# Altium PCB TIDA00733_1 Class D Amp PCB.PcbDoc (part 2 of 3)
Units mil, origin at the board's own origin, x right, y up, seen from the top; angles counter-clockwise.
Board outline 5700 x 4500 mil, 4 copper layers (Top Layer, Signal Layer 1, Signal Layer 2, Bottom Layer), stack 61.668 mil thick; 305 components, 186 nets, 894 pads, 1056 vias.
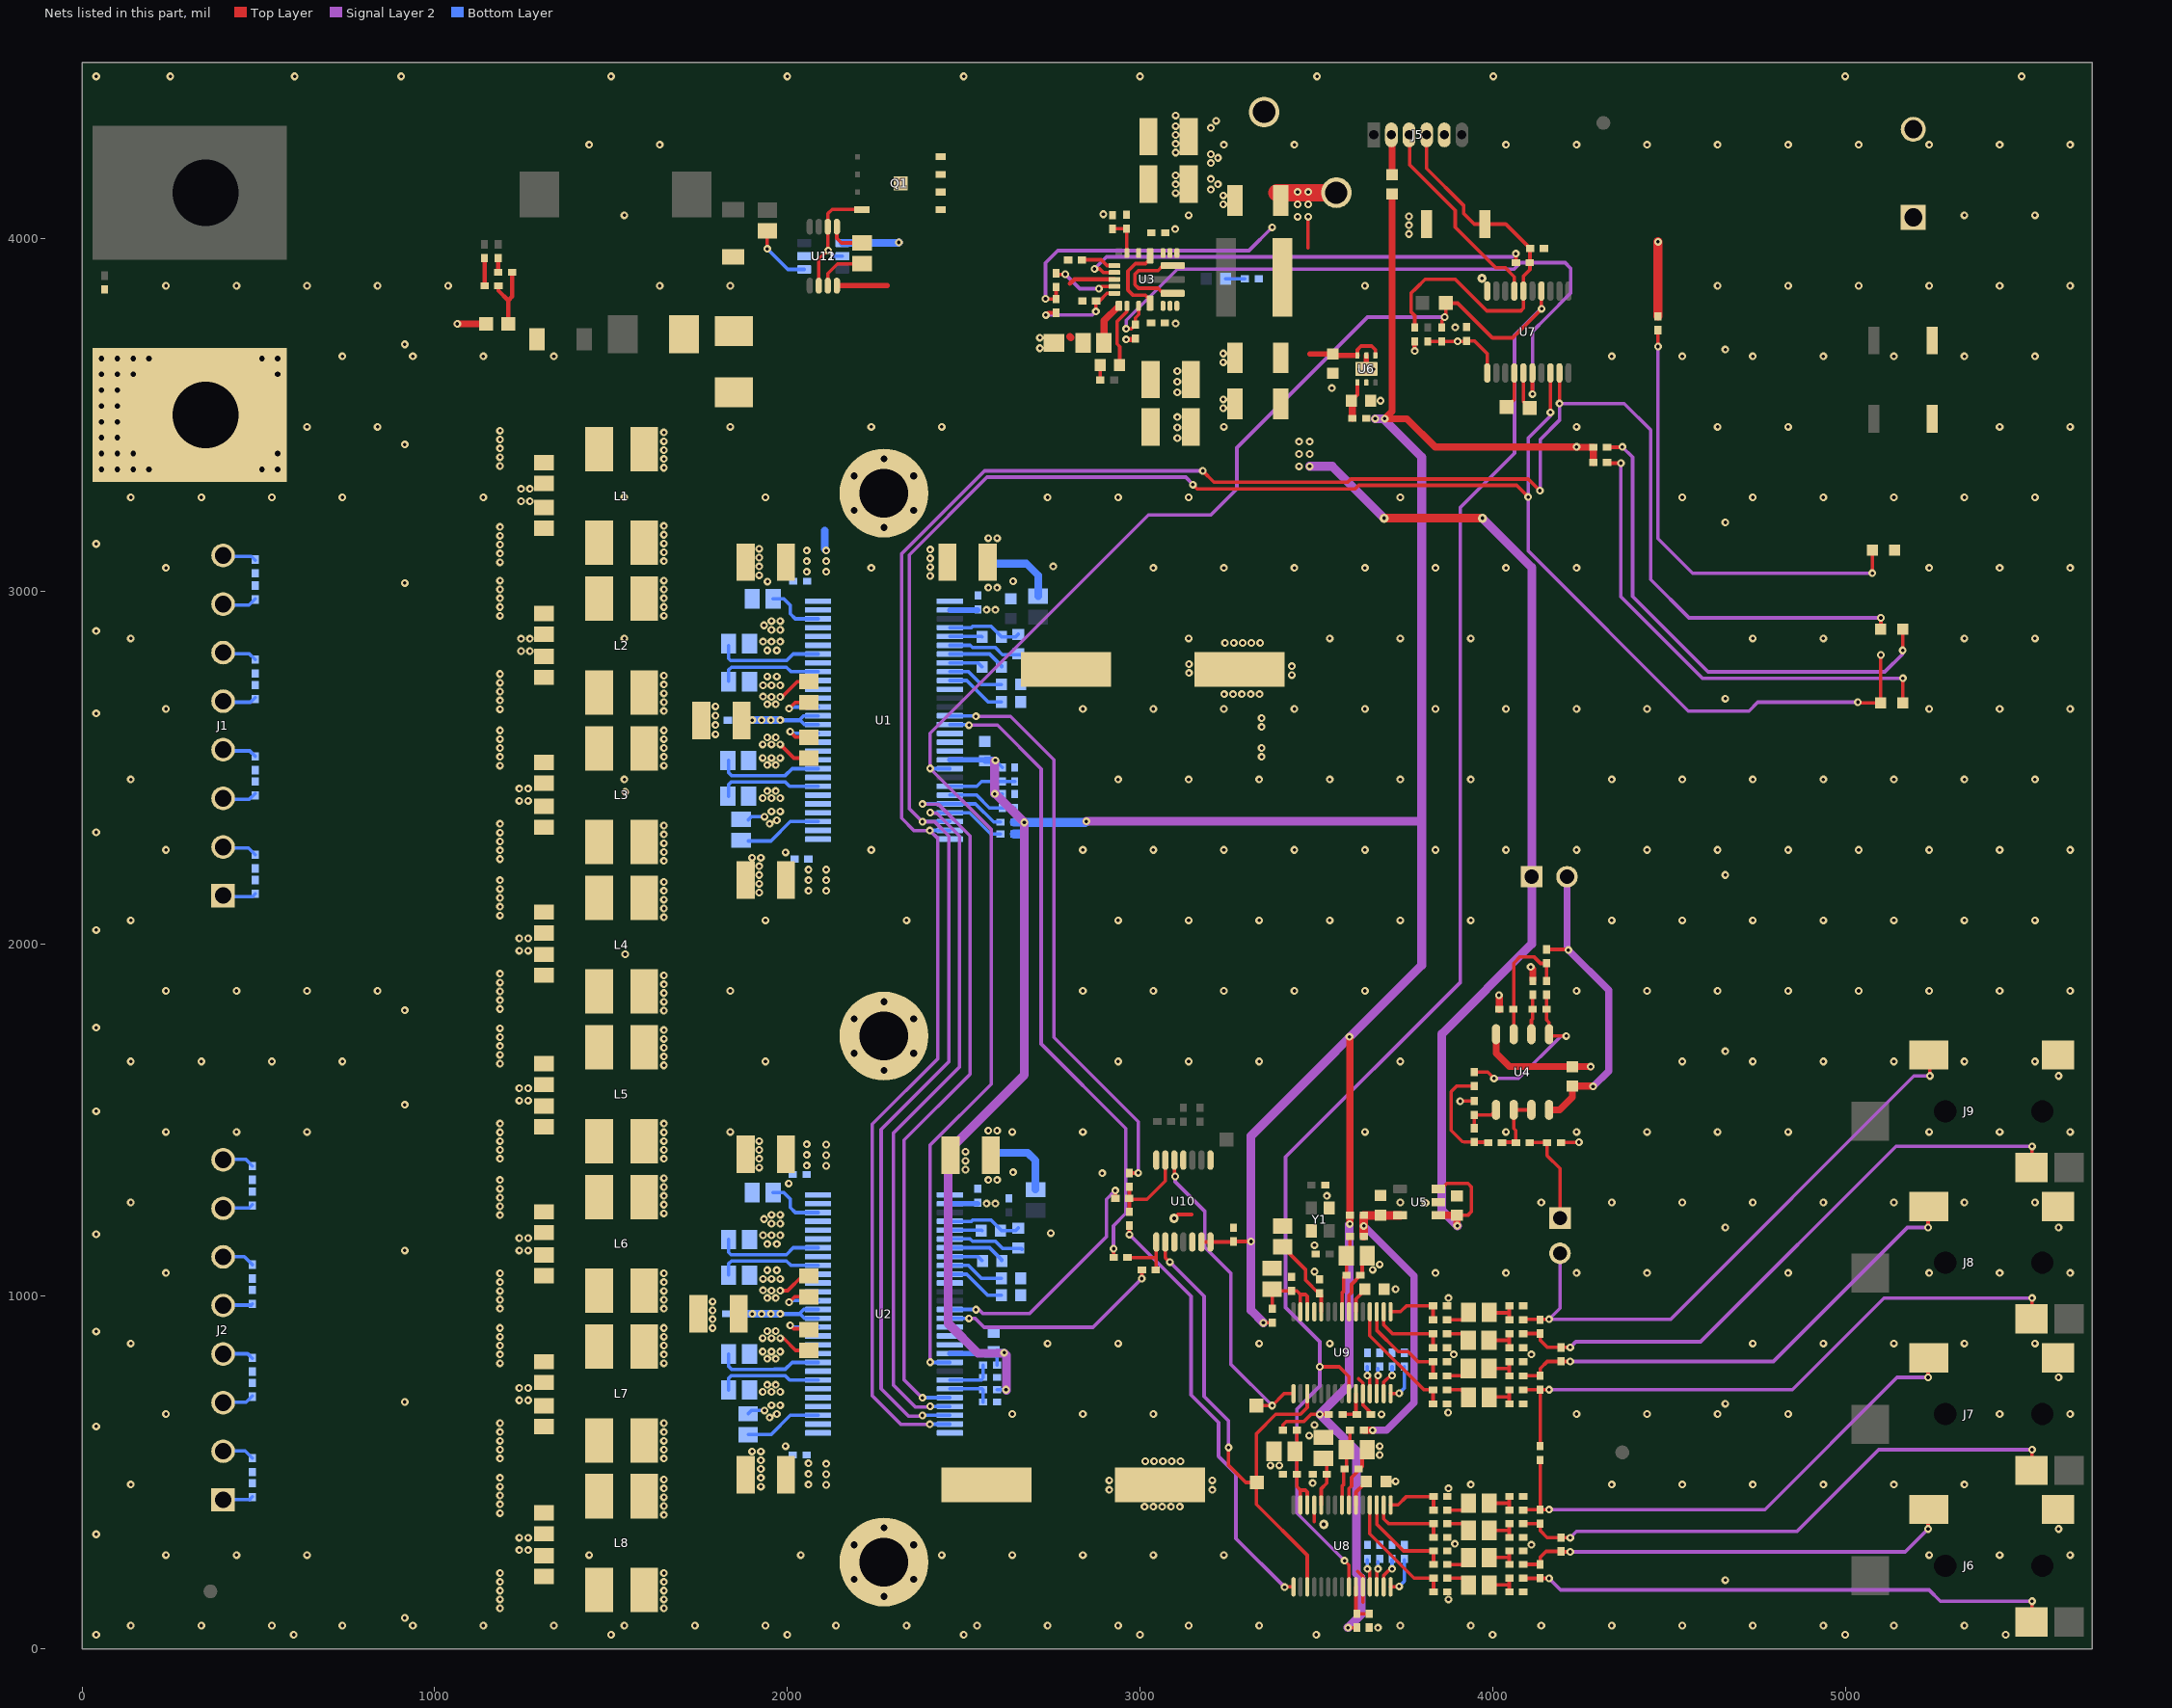
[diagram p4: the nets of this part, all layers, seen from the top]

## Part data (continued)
R35 R36 R51 R52: "Ferrite Bead, 600 ohm @ 100 MHz, 0.5 A, 0402", Manufacturer=MuRata, Supplier Part Number 1=490-5441-1-ND, Value1="0.34 ohm", Value2=0.5A, ValueDisplayed="600 ohm"
R40 R42 R44 R46 R56 R58 R60 R62: "RES, 100, 1%, 0.063 W, 0402", Manufacturer=Vishay-Dale, Power_W=0.063, Supplier Part Number 1=541-100LCT-ND, TempCo="100 ppm/C", Tolerance_%=1, Value1=1%, Value2=0.063W, Value_Code=100R, ValueDisplayed=100
R67 R68 R69 R70 R71 R72 R80 R81: "RES, 54.9, 1%, 0.063 W, 0402", Manufacturer=Vishay-Dale, Power_W=0.063, Supplier Part Number 1=541-54.9LCT-ND, TempCo="100 ppm/C", Tolerance_%=1, Value1=1%, Value2=0.063W, Value_Code=54R9, ValueDisplayed=54.9
R82: "RES, 221, 1%, 0.063 W, 0402", Manufacturer=Vishay-Dale, Power_W=0.063, Supplier Part Number 1=541-221LCT-ND, TempCo="100 ppm/C", Tolerance_%=1, Value1=1%, Value2=0.063W, Value_Code=221R, ValueDisplayed=221
R86: "RES, 0.51, 1%, 0.1 W, AEC-Q200 Grade 1, 0603", Manufacturer=Panasonic, Power_W=0.1, Supplier Part Number 1=P.51AJCT-ND, TempCo="300 ppm/C", Tolerance_%=1, Value1=1%, Value2=0.1W, Value_Code=R510, ValueDisplayed=0.51
S1 S2 S3: "Switch, Push Button, SMD", CurrentRating_mA=50, Manufacturer=Alps, Supplier Part Number 1=688-SKRKAE
T1 T2: "Terminal 50A Lug", Manufacturer=Panduit, Supplier Part Number 1=CB35-36-CY-ND, Voltage_V=600
TP3: "Test Point, Multipurpose, Black, TH", Color=Black, Manufacturer=Keystone, Supplier Part Number 1=36-5011-ND
TP5: "Test Point, Multipurpose, Red, TH", Color=Red, Manufacturer=Keystone, Supplier Part Number 1=36-5010-ND
TP6 TP7 TP8 TP9 TP12 TP14 TP15: library part PAD_1MM_SQUARE, "1.0x1.0mm pad, square, SMD", Manufacturer=Any
U1 U2: "Four-Channel Digital Input Automotive Digital Amplifier, DKQ0056A", Alternate Manufacturer="Texas Instruments"
U3: "2.5/3.5A Synchronous Buck Regulator for Automotive Applications, RNL0022A", Alternate Manufacturer="Texas Instruments", Alternate PartNumber=LM53635LQRNLTQ1
U4: "Automotive Catalog Low-Power Rail-to-Rail Input / Output Operational Amplifier with Shutdown, 2.7 to 6 V, -40 to 125 degC, 8-pin SOIC (D0008A), Green (RoHS & no Sb/Br)", Alternate Manufacturer="Texas Instruments", Alternate PartNumber=Equivalent, Supplier Part Number 1=296-17738-2-ND, Total Supply Voltage(Max)(+5V is 5, +/-5V is 10)=6, Total Supply Voltage(Min)(+5V is 5, +/-5V is 10)=2.7
U5: "Automotive 250-mA, Ultra-Low-Noise, Low-IQ LDO, DBV0005A (SOT-23-5)", Alternate Manufacturer="Texas Instruments"
U6: "Ultra Low-Noise, 500-mA Linear Regulator for RF and Analog Circuits - Requires No Bypass Capacitor, DRV0006A", Alternate Manufacturer="Texas Instruments", Alternate PartNumber=LP5912Q3.3DRVTQ1
U7: "MIXED SIGNAL MICROCONTROLLER, PW0020A", Alternate Manufacturer="Texas Instruments", Alternate PartNumber=MSP430G2332QPW2EP
U8 U9: "110 dB 4ch Audio ADCs With Universal Front End, DBT0030A", Alternate Manufacturer="Texas Instruments"
U10: "QUADRUPLE BUS BUFFER GATE WITH 3-STATE OUTPUTS, PW0014A", Alternate Manufacturer="Texas Instruments"
U11: library part CMP-0076397-1, "Zero Iq Reverse Polarity Protection Smart Diode Controller, DGK0008A (VSSOP-8)", Alternate Manufacturer="Texas Instruments"
U12: library part CMP-0013281-3, "Low Iq Always ON Smart Diode Controller, DDC0006A (SOT-6)", Alternate Manufacturer="Texas Instruments"
Y1: "Crystal, 24.576 MHz,  SMD", Frequency_Fixed="24.576 MHz", Frequency Stability=±50ppm, Manufacturer="Abracon Corporation", Supplier Part Number 1=ABM10AIG-24.576MHZ-J4Z-T3-ND
ZZ1: library part AssemblyNoteLabel

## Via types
v1: diameter 22, hole 10, Top Layer to Bottom Layer, tented both sides, 975 vias
v2: diameter 32, hole 16, Top Layer to Bottom Layer, tented both sides, 56 vias
v3: diameter 39.37, hole 19.68, Top Layer to Bottom Layer, tented both sides, 18 vias
v4: diameter 26, hole 10, Top Layer to Bottom Layer, 3 vias
v5: diameter 19.68, hole 7.87, Top Layer to Bottom Layer, tented both sides, 2 vias
v6: diameter 26, hole 10, Top Layer to Bottom Layer, tented both sides, 2 vias

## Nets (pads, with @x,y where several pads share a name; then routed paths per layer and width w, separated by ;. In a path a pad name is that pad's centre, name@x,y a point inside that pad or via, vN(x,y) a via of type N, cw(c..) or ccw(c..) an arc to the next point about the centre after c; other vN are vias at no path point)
1L: C135.1 R56.2 U9.3 | length 289.2
  Top Layer w10: U9.3@3671.43,956.14 3671.43,903.57 3732,843 3760,843 3788.86,814.14 C135.1@3831.31,814.14 R56.2@3831.31,774.43
1P8V: C125.1 C126.1 U9.11 | length 230.7
  Top Layer w10: C126.1@3404.76,1140.24 3470,1075 3470,1045 3506.69,1008.32 C125.1@3509,1008.32 3513.94,1003.37 U9.11@3513.94,956.14
1P8V_2: C105.1 C106.1 U8.11 | length 143.2
  Top Layer w10: U8.11@3513.94,408.14 3513.94,453.94 3529.69,469.68 C105.1@3529.69,495 C106.1@3529.69,544.79
1R: C133.1 R58.2 U9.4 | length 350.8
  Top Layer w10: U9.4@3651.74,956.14 3651.74,888.26 3805.29,734.71 R58.2@3831.31,734.71 C133.1@3831.31,695
2L: C136.1 R60.2 U9.1 | length 167.2
  Top Layer w10: U9.1@3710.8,956.14 3738.86,956.14 3755.72,973 C136.1@3831.31,973 R60.2@3831.31,933.29
2R: C134.1 R62.2 U9.2 | length 227.7
  Top Layer w10: U9.2@3691.11,956.14 3691.11,918.89 3716.43,893.57 R62.2@3831.31,893.57 C134.1@3831.31,853.86
3L: C115.1 R40.2 U8.3 | length 285.5
  Top Layer w10: U8.3@3671.43,408.14 3671.43,353.57 3747.29,277.71 C115.1@3832.31,277.71 R40.2@3832.31,239.14
3R: C113.1 R42.2 U8.4 | length 358.2
  Top Layer w10: U8.4@3651.74,408.14 3651.74,326 3777.17,200.57 R42.2@3832.31,200.57 ; C113.1@3832.31,162 R42.2@3832.31,200.57 ; R42.2@3837.31,200.57 R42.2@3832.31,200.57
3V3_1865A1: C120.1 C121.1 R52.1 U9.8 | length 223.1
  Top Layer w10: U9.8@3573,956.14 3573,1009.32 3578,1014.32 3578,1052.68 C121.1@3585.31,1060 3585.31,1114.84 C120.1@3585.47,1115 3595.31,1124.84 R52.1@3595.31,1170
3V3_1865A2: C100.1 C101.1 R36.1 U8.8 | length 223.1
  Top Layer w10: U8.8@3573,408.14 3573,461.32 3578,466.32 3578,504.68 3585.31,512 3585.31,566.84 3585.47,567 3595.31,576.84 R36.1@3595.31,622
3V3_1865D1: C117.1 C118.1 R51.1 U9.13 U9.14 | length 256.9
  Top Layer w10: R51.1@3375,964.68 C117.1@3375,1020.47 3380.16,1015.32 C118.1@3430,1015.32 3444.69,1015.32 3454.89,1005.11 ; U9.14@3454.89,956.14 3454.89,1005.11 ; U9.13@3474.57,956.14 3474.57,1000.43 3469.89,1005.11 3454.89,1005.11
3V3_1865D2: C97.1 C99.1 R35.1 U8.13 U8.14 | length 274.6
  Top Layer w10: R35.1@3444.69,620 3444.69,564.16 3444.53,564 3444.69,563.84 C99.1@3444.69,495 3444.69,460.32 3454.89,450.11 ; U8.14@3454.89,408.14 3454.89,450.11 ; U8.13@3474.57,408.14 3474.57,444.57 3469.04,450.11 3454.89,450.11
4L: C116.1 R44.2 U8.1 | length 170
  Top Layer w10: U8.1@3710.8,408.14 3731.86,408.14 3755.72,432 C116.1@3832.31,432 R44.2@3832.31,393.43
4R: C114.1 R46.2 U8.2 | length 229.8
  Top Layer w10: U8.2@3691.11,408.14 3691.11,368.89 3705.14,354.86 R46.2@3837.31,354.86 ; C114.1@3832.31,316.29 R46.2@3832.31,354.86
5_BIAS: C146.1 R22.1 U3.22 | length 268.8
  Top Layer w10: v1(2733,3783) 2739.32,3789.31 R22.1@2762,3789.31 ; v1(2875,3793) 2875,3822.31 C146.1@2875.69,3823 2885,3823 2906.63,3844.63 U3.22@2927.46,3844.63
  Signal Layer 2 w10: v1(2733,3783) 2865,3783 v1(2875,3793)
5_BOOT: C84.2 U3.2 | length 182.9
  Top Layer w10: C84.2@2942.56,3641 2942.56,3693.44 2935,3701 2935,3765 2962.9,3792.9 U3.2@2962.9,3809.2
+3P3V: C15.1 C55.1 C95.1 C139.1 R3.1 R5.2 R6.2 R7.1 R10.1 R11.1 R14.1 R16.1 R19.2 R21.2 R29.2 R30.2 R31.2 R33.2 R35.2 R37.2 R51.2 R53.2 U1.19 U2.19 U7.1 U10.13 U10.14 | length 10179
  Top Layer w10: U10.13@3174.18,1153.86 U10.14@3199.77,1153.86 3263.54,1153.86 C139.1@3265,1155.32 v1(3314.69,1155.32) ; v1(3350,925) 3350.31,925.31 R51.2@3375,925.31 ; R35.2@3405.31,620 3405.31,635.31 3415,645 3465,645 3485,665 v1(3510,665) R53.2@3535.31,665 ; v1(3590,60) 3614.69,60 R37.2@3615,59.69 ; R30.2@3816,3708.31 R29.2@3856,3708.31 v1(3901,3708.31) 3925,3708.31 C95.1@3926,3709.31 3948.69,3709.31 3984.84,3673.16 U7.1@3984.84,3618.86
  Top Layer w12: v1(3779,3681) R33.2@3779,3708.31
  Top Layer w20: v1(3594,1736) 3595,1735 v1(3595,1205) ; R31.2@3715,4126.44 3715,3510 v1(3694,3489) 3757,3489 3837,3409 v1(4238,3409) 4239,3408 R11.1@4285.31,3408 R10.1@4285.31,3365
  Signal Layer 2 w25: 2456,1412 2672,1628 v1(2672,2344) 2591,2425 v1(2588,2425) v1@2588,2518 ; 2456,1413 2456,923 2541,838 v1@2616,838 ; v1@2621,733 v1@2621,833 ; v1(2848,2347) 3796,2347 3799,2344 ; v1(3350,925) 3314.69,960.32 v1(3314.69,1155.32) 3314.69,1454.68 3799,1939 3799,2344 ; v1(3590,60) 3627,97 3627,200.74 3613.7,214.04 3613.7,240.26 3614,240.56 3614,561 v1(3510,665) 3593,748 v1@3593,1203 ; v1(3667,3489) v1(3694,3489) 3694,3485 3799,3380 3799,2344
  Bottom Layer w10: 2556.94,837.5 2560,834.44 2561.56,836 ; C15.1@2556.94,2521.5 C15.1@2560,2518.44 C15.1@2561.56,2520 ; v1@2589.68,2424.69 R7.1@2610,2424.69 ; v1(2590,2520) 2610,2500 R3.1@2610,2499.69 ; C55.1@2594,840 2590,836 2594.68,831.32 R14.1@2594.68,805 ; R16.1@2594.68,735 v1(2620,735)
  Bottom Layer w15: U2.19@2461.01,837.5 2556.94,837.5 ; U1.19@2461.01,2521.5 C15.1@2556.94,2521.5
  Bottom Layer w20: 2561.56,836 C55.1@2590,836 ; C15.1@2561.56,2520 v1(2590,2520) ; C55.1@2594,840 v1(2615,840)
  Bottom Layer w25: R5.2@2643.69,2311 2671,2311 2672,2312 v1(2672,2344) ; R6.2@2643.69,2345 2671,2345 v1(2672,2344) ; v1@2845,2344 v1(2672,2344)
+3P3V_A: C143.1 R21.1 R36.2 R52.2 U5.5 | length 898
  Top Layer w20: R36.2@3634.69,620 v1(3660,620)
  Top Layer w25: R52.2@3634.69,1170 v1(3634.69,1199.69) 3634.69,1229.6 U5.5@3737.87,1229.6
  Signal Layer 2 w20: v1(3634.69,1199.69) 3777,1057.37 3777,698 3699,620 v1(3660,620)
+5V: C91.1 C92.1 C93.1 C142.1 C145.1 J3.1 J10.1 L9.2 R18.2 R22.2 R25.2 TP5.1 U5.1 U5.3 U6.4 U6.6 | length 4567.1
  Top Layer w10: v1(2732,3829) 2732.31,3828.69 R22.2@2762,3828.69 R18.2@2762,3858.31 ; 3476,3974 3476,4049 ; v1(3481,3389) v1@3481.31,3388.69 ; C145.1@3546,3671.56 C145.1@3547.97,3669.59 ; C145.1@3547,3672.56 C145.1@3551.17,3668.39 ; U6.6@3616.41,3668.39 3616.41,3684.41 3627,3695 3657,3695 3667.59,3684.41 U6.4@3667.59,3668.39 ; U5.3@3846.13,1304.4 3854.4,1304.4 3870,1320 3930,1320 3940,1310 3940,1240 3929.44,1229.44 C142.1@3899,1229.44
  Top Layer w15: 3482,3673 C145.1@3539.44,3673 ; C145.1@3551.17,3668.39 U6.6@3616.41,3668.39
  Top Layer w20: U5.1@3846.13,1229.6 3898.84,1229.6 C142.1@3899,1229.44 3899,1201 v1(3900,1200)
  Top Layer w25: v6(3692,3207) v6(3971,3207) ; R25.2@4469,3779.69 v1(4469,3991)
  Top Layer w50: C91.1@3389,4130 TP5.1@3557,4130
  Signal Layer 2 w10: v1(2732,3829) 2732,3931 2767,3966 3309,3966 v1(3375,4032)
  Signal Layer 2 w25: v1(3481,3354) 3545,3354 v6(3692,3207) ; v1(3900,1200) 3856,1244 3856,1744 4111,1999 J3.1@4111,2190 4111,3067 v6(3971,3207)
  other v1: 3451,3354 3451,3389 3451,3424 3481,3424 3447,4062 3477,4062 3447,4097 3477,4097 3447,4132 3477,4132
AGND: C94.2 C146.2 NTG.1 U3.20 | length 136.1
  Top Layer w12: 2801.31,3871.91 2814.2,3884.8 2926.66,3884.8 U3.20@2927.46,3884
  Top Layer w20: 2801,3722 2804,3719
AREF: C21.2 C23.2 U1.4 | length 211
  Bottom Layer w10: U1.4@2461.01,2896.5 2521.5,2896.5 2525,2900 2577.56,2900 C21.2@2607.56,2870 2647.44,2870 C23.2@2655,2877.56
AREF2: C61.2 C63.2 U2.4 | length 211
  Bottom Layer w10: U2.4@2461.01,1212.5 2521.5,1212.5 2525,1216 2577.56,1216 2607.56,1186 2647.44,1186 C63.2@2655,1193.56
AVDD2_GND: C66.2 U2.7 | length 163.1
  Bottom Layer w10: U2.7@2461.01,1137.5 2573.5,1137.5 2607.56,1103.44 C66.2@2607.56,1101
AVDD_GND: C24.2 U1.7 | length 163.1
  Bottom Layer w10: U1.7@2461.01,2821.5 2573.5,2821.5 2607.56,2787.44 C24.2@2607.56,2785
DOUT: TP12.1 U8.18 U9.18 U10.9 | length 1506.7
  Top Layer w10: U10.9@3071.82,1153.86 3071.82,1109.18 3084,1097 v1(3085,1097) ; v1(3251,571) 3251,521 3300,472 TP12.1@3331,472 ; TP12.1@3330,465 3330,410 3474.57,265.43 U8.18@3474.57,175.86 ; TP12.1@3330,475 3330,610 3385,665 3455,665 3474.57,684.57 U9.18@3474.57,723.86
  Signal Layer 2 w10: v1(3085,1097) 3182,1000 3182,716 3251,647 v1(3251,571)
DOUT_B: R80.1 R81.1 U10.8 | length 155.4
  Top Layer w10: R80.1@2964.69,1110 3046.23,1110 ; R81.1@3046.23,1080 3046.23,1110 ; U10.8@3046.23,1153.86 3046.23,1110
DOUT_T1: R80.2 U1.15 | length 1816.3
  Top Layer w10: v1@2925,1125.31 v1@2925.31,1125 ; R80.2@2925.31,1110 v1(2925.31,1134.69)
  Signal Layer 2 w10: v1(2515,2620) 2596,2620 2720,2496 2720,1716 2960,1476 2960,1235 2925,1200 v1@2925,1134.69
  Bottom Layer w10: U1.15@2461.01,2621.5 2518.5,2621.5 v1@2520,2620
DOUT_T2: R81.2 U2.15 | length 636.8
  Top Layer w10: v1(3005,1050) 3005.31,1050.31 R81.2@3005.31,1075
  Signal Layer 2 w10: v1(2515,937) 2533,937 2558,912 2867,912 v1(3005,1050)
  Bottom Layer w10: U2.15@2461.01,937.5 2514.5,937.5 v1(2515,937)
FB5: R18.1 U3.21 | length 189.2
  Top Layer w10: R18.1@2762,3897.69 v1@2789.32,3897.69 ; v1(2788,3899) v1@2789.32,3897.69 ; v1@2790,3897 v1@2789.32,3897.69 ; v1(2883.51,3858) 2885,3858 2891.31,3864.31 U3.21@2927.46,3864.31
  Signal Layer 2 w10: v1(2788,3899) 2829,3858 v1(2883.51,3858)
FPWM: R24.2 R28.1 U3.16 | length 110.3
  Top Layer w10: R28.1@2922,4027.31 2923,4028.31 R24.2@2962,4028.31 2962.9,4027.42 U3.16@2962.9,3958.8
GND: C1.2 C2.2 C3.2 C4.2 C5.2 C6.2 C7.2 C8.2 C9.2 C10.2 C11.2 C12.2 C13.2 C15.2 C17.2 C18.2 C20.2 C25.2 C26.2 C29.2 C30.2 C31.2 C32.2 C35.2 C36.2 C37.2 C38.2 C39.2 C40.2 C41.2 C42.2 C43.2 C44.2 C45.2 C46.2 C47.2 C48.2 C49.2 C50.2 C51.2 C52.2 C53.2 C55.2 C57.2 C58.2 C60.2 C64.2 C65.2 C69.2 C70.2 C71.2 C72.2 C75.2 C76.2 C77.2 C78.2 C79.2 C80.2 C82.2 C83.2 C85.2 C86.2 C87.2 C88.2 C89.2 C90.2 C91.2 C92.2 C93.2 C95.2 C96.2 C97.2 C99.2 C100.2 C101.2 C105.2 C106.2 C107.2 C108.2 C109.2 C110.2 C111.2 C113.2 C114.2 C115.2 C116.2 C117.2 C118.2 C119.2 C120.2 C121.2 C125.2 C126.2 C127.2 C128.2 C129.2 C130.2 C131.2 C133.2 C134.2 C135.2 C136.2 C137.2 C138.2 C139.2 C140.2 C142.2 C143.2 C144.2 C145.2 C148.2 C149.2 D6.1 D7.1 J5.5 J6.1 J7.1 J8.1 J9.1 J10.2 MH1.1 MH2.1 MH3.1 NTG.2 R4.2 R8.2 R13.1 R15.2 R17.2 R20.1 R28.2 R38.1 R47.1 R48.1 R49.1 R50.1 R54.1 R63.1 R64.1 R65.1 R66.1 R82.1 R85.1 R86.1 S1.2 S2.2 S3.2 T2.1 TP3.1 U1.1 U1.11 U1.16 U1.17 U1.18 U1.28 U1.33 U1.36 U1.39 U1.46 U1.49 U1.52 U2.1 U2.11 U2.16 U2.17 U2.18 U2.28 U2.33 U2.36 U2.39 U2.46 U2.49 U2.52 U3.5 U3.6 U3.7 U3.8 U3.10 U3.11 U3.12 U3.13 U4.4 U5.2 U6.2 U6.5 U6.7@3642,3630 U7.20 U8.7 U8.12 U8.26 U9.7 U9.12 U9.26 U10.1 U10.4 U10.7 U10.10 U10.12 U12.2 Y1.2 Y1.4 | length 1593.6
  Top Layer w10: R20.1@2984.69,3714 R20.1@2987,3716.31 ; U3.8@3092.82,3844.63 3065.37,3844.63 3051,3859 2996,3859 2986,3869 2986,3899 2996,3909 3051,3909 3065.37,3923.37 U3.10@3092.82,3923.37 ; v4(3097,1221) 3108,1232 3147,1232 ; 3494.26,361.26 U8.12@3494.26,408.14 ; U8.7@3592.69,408.14 3592.69,454.69 3600,462 3600,486 3624.69,510.69 3624.69,512 3630,517.31 3630,552.47 C100.2@3644.53,567 ; U9.7@3592.69,956.14 3592.69,1002.69 3600,1010 3600,1034 3624.69,1058.69 C121.2@3624.69,1060 3630,1065.31 3630,1100.47 C120.2@3644.53,1115 ; 3617.27,220 3632.06,205.22 3632.06,133 ; 3620,766 3632.06,753.94 3632.06,691.94 3654.69,669.32 R54.1@3654.69,665 ; v1(3908,1553) 3908.69,1553.69 C149.2@3948,1553.69 ; R82.1@4193.69,1436 4244,1436 v1(4245,1437)
  Top Layer w15: v1(2961,3714) R20.1@2984.69,3714 ; U6.7@3642,3630 U6.5@3642,3668.39
  Top Layer w20: v1(1064,3758) R86.1@1145.5,3758 ; U4.4@4010,1743.28 4010,1689 4047.44,1651.56 C119.2@4226,1651.56 4277.44,1651.56 v1(4278,1651) ; v1(4018,1854) 4019.31,1852.68 R85.1@4019.31,1814 ; v1(4108,1934) 4114,1928 C148.2@4114,1894.68
  other v1: 40,40 600,40 1500,40 2000,40 2500,40 3000,40 3500,40 4000,40 5000,40 5455,40 3675,60 138,66 338,66 538,66 738,66 938,66 1138,66 1338,66 1538,66 1738,66 1938,66 2138,66 2338,66 2538,66 2738,66 2938,66 3138,66 3338,66 3738,66 3938,66 4138,66 4338,66 4538,66 4738,66 4938,66 5138,66 5338,66 915,88 3875,140 4660,195 238,266 438,266 638,266 1438,266 2038,266 2438,266 2638,266 2838,266 3038,266 3238,266 5238,266 5438,266 5638,266 1240,280 1265,280 4110,295 3893,298 1240,315 1265,315 40,325 5605,340 3013,403 3038,403 3063,403 3088,403 3113,403 2913,451 3205,451 3875,455 1925,460 138,466 3938,466 4338,466 4538,466 4738,466 4938,466 5138,466 5338,466 3490,470 3725,475 2913,478 3205,478 1925,485 1925,510 3370,520 3395,520 3015,532 3040,532 3065,532 3090,532 3115,532 1925,535 3680,550 1900,560 1925,560 1995,575 3680,575 3480,605 40,631 3495,635 3685,665 238,666 2638,666 2838,666 3038,666 4238,666 4438,666 4638,666 4838,666 5438,666 5638,666 3874,670 4660,695 915,700 1240,705 1265,705 1240,740 1265,740 5605,770 3890,835 4110,835 138,866 2738,866 2938,866 3338,866 3538,866 4738,866 4938,866 5138,866 5338,866 5538,866 40,900 1788,910 1788,935 1788,960 1788,985 3875,995 3725,1020 238,1066 3838,1066 4038,1066 4238,1066 4438,1066 4838,1066 5238,1066 5438,1066 5638,1066 3495,1070 3660,1075 3680,1090 915,1130 1240,1130 1265,1130 3495,1145 1240,1165 1265,1165 40,1176 2747,1179 4660,1195 5605,1195 3810,1265 138,1266 3738,1266 4138,1266 4338,1266 4538,1266 4738,1266 4938,1266 5138,1266 5338,1266 5538,1266 3530,1285 2004,1320 2893,1349 2640,1352 2505,1359 1920,1365 2505,1384 1920,1390 2505,1410 1920,1415 1920,1440 238,1466 438,1466 638,1466 1838,1466 2638,1466 2838,1466 3638,1466 4038,1466 4238,1466 4438,1466 4638,1466 4838,1466 5238,1466 5438,1466 5638,1466 40,1525 915,1543 1240,1555 1265,1555 1240,1590 1265,1590 5605,1625 138,1666 338,1666 538,1666 738,1666 1938,1666 2938,1666 3138,1666 3338,1666 3738,1666 4538,1666 4738,1666 4938,1666 5138,1666 5338,1666 5538,1666 4660,1695 40,1762 915,1811 238,1866 438,1866 638,1866 838,1866 1838,1866 2838,1866 3038,1866 3238,1866 3438,1866 3638,1866 4238,1866 4438,1866 4638,1866 4838,1866 5038,1866 5238,1866 5438,1866 5638,1866 1540,1970 1240,1980 1265,1980 1240,2015 1265,2015 40,2039 138,2066 1938,2066 2338,2066 2938,2066 3138,2066 3338,2066 3538,2066 3738,2066 3938,2066 4338,2066 4538,2066 4738,2066 4938,2066 5138,2066 5338,2066 5538,2066 1920,2145 1920,2170 1920,2195 4660,2195 1920,2220 1900,2244 1925,2244 1995,2259 238,2266 2238,2266 2838,2266 3038,2266 3238,2266 3438,2266 3638,2266 3838,2266 4038,2266 4238,2266 4438,2266 4638,2266 4838,2266 5038,2266 5238,2266 5438,2266 5638,2266 40,2316 1240,2405 1265,2405 1540,2430 1240,2440 1265,2440 138,2466 1538,2466 2938,2466 3138,2466 3338,2466 3538,2466 3738,2466 3938,2466 4338,2466 4538,2466 4738,2466 4938,2466 5138,2466 5338,2466 5538,2466 3345,2530 3345,2555 1796,2594 3345,2615 1796,2620.33 3345,2640 1796,2646.67 40,2653 238,2666 2838,2666 3038,2666 3238,2666 3438,2666 3638,2666 3838,2666 4038,2666 4238,2666 4438,2666 5238,2666 5438,2666 5638,2666 1796,2673 4660,2695 3239,2708 3264,2708 3289,2708 3314,2708 3339,2708 3430.49,2762 3139,2768 3430.49,2787 3139,2793 1245,2830 1270,2830 3241,2853 3266,2853 3291,2853 3316,2853 3341,2853 1245,2865 1270,2865 138,2866 1538,2866 3138,2866 3538,2866 3738,2866 3938,2866 4738,2866 4938,2866 5338,2866 5538,2866 40,2887 915,3023 1944,3027 2640,3028 2405,3043 1920,3045 238,3066 2238,3066 3038,3066 3238,3066 3438,3066 3638,3066 3838,3066 4038,3066 4238,3066 5238,3066 5438,3066 5638,3066 2405,3068 1920,3070 2754,3070 2405,3093 1920,3095 2405,3118 1920,3120 40,3134 4660,3195 1245,3255 1270,3255 138,3266 338,3266 538,3266 738,3266 1138,3266 1538,3266 1938,3266 2738,3266 2938,3266 3138,3266 3738,3266 4538,3266 4738,3266 4938,3266 5138,3266 5338,3266 5538,3266 1245,3290 1270,3290 915,3416 3106,3434 3106,3464 638,3466 838,3466 1838,3466 2238,3466 2438,3466 3238,3466 4238,3466 4638,3466 4838,3466 5438,3466 5638,3466 3106,3494 3236,3519 3682,3540 3236,3544 3106,3564 3544,3576 3106,3594 3106,3624 3236,3649 738,3666 938,3666 1138,3666 1338,3666 4338,3666 4538,3666 4738,3666 4938,3666 5138,3666 5338,3666 5538,3666 3236,3674 4660,3685 2716,3689 915,3700 2716,3719 3894,3748 3101,3759 238,3866 438,3866 638,3866 838,3866 1038,3866 1638,3866 1838,3866 3638,3866 4638,3866 4838,3866 5038,3866 5238,3866 5438,3866 5638,3866 3763,4013 3100,4027 3763,4038 3763,4063 1538,4066 3138,4066 5338,4066 5538,4066 2896,4069 3236,4097 3236,4122 3101,4129 3201,4139 3101,4154 3221,4154 3201,4169 3101,4179 3201,4214 3221,4229 3201,4239 3101,4244 1438,4266 1638,4266 3238,4266 3438,4266 4038,4266 4238,4266 4438,4266 4638,4266 4838,4266 5038,4266 5238,4266 5438,4266 5638,4266 3101,4269 3101,4294 3201,4314 3101,4319 3216,4334 3101,4349 40,4460 250,4460 603,4460 905,4460 1500,4460 2000,4460 2500,4460 3000,4460 3502,4460 4002,4460 5000,4460 5500,4460
  other v2: 55,3345 100,3345 145,3345 190,3345 510,3345 555,3345 55,3390 100,3390 145,3390 555,3390 55,3435 100,3435 55,3480 100,3480 55,3525 100,3525 55,3570 100,3570 55,3615 100,3615 145,3615 555,3615 55,3660 100,3660 145,3660 190,3660 510,3660 555,3660
  other v3: 2274,148.56 2189.61,197.28 2358.39,197.28 2189.61,294.72 2358.39,294.72 2274,343.44 2274,1640.56 2189.61,1689.28 2358.39,1689.28 2189.61,1786.72 2358.39,1786.72 2274,1835.44 2274,3180.56 2189.61,3229.28 2358.39,3229.28 2189.61,3326.72 2358.39,3326.72 2274,3375.44
  other v4: 3521,353 3970,3887
  other v5: 3620.35,3630 3663.65,3630
I2C_A0: R3.2 R4.1 U1.22 | length 189.7
  Bottom Layer w10: U1.22@2461.01,2446.5 2537.5,2446.5 2551.32,2460.31 R4.1@2645,2460.31
I2C_A1: R7.2 R8.1 U1.23 | length 199
  Bottom Layer w10: U1.23@2461.01,2421.5 2536.5,2421.5 2572.68,2385.31 R8.1@2645,2385.31
I2CB_A0: R14.2 R15.1 U2.22 | length 125.3
  Bottom Layer w10: U2.22@2461.01,762.5 R15.1@2551.32,762.5 ; R15.1@2555.32,770 R14.2@2555.31,805
I2CB_A1: R16.2 R17.1 U2.23 | length 126.5
  Bottom Layer w10: U2.23@2461.01,737.5 R16.2@2552.5,737.5 ; R17.1@2555.32,700 R16.2@2555.31,735
I2S_ADSEL_1865_1: R53.1 R54.2 U9.25 | length 100.7
  Top Layer w10: R53.1@3574.69,665 R54.2@3615.31,665 3612.37,667.94 U9.25@3612.37,723.86
I2S_ADSEL_1865_2: R37.1 R38.2 U8.25 | length 117.3
  Top Layer w10: R37.1@3612.37,102.31 U8.25@3612.37,175.86 ; R37.1@3615,99.68 3655,99.69 R38.2@3652.37,102.31
IN1: J8.3 R55.2 R73.2 R74.2 | length 1394.9
  Top Layer w10: R55.2@4086.69,774.43 4086.94,774.69 R73.2@4135,774.69 4135,795 4155,815 v1(4220,815) ; v1(5235,1195) 5235,1253.33 J8.3@5236.5,1254.83
  Signal Layer 2 w10: v1(4220,815) 4796,815 5176,1195 v1(5235,1195)
IN1_ATTN: C122.1 R55.1 R63.2 | length 96.5
  Top Layer w10: C122.1@3990.53,795 4047.31,795 ; R55.1@4047.31,774.43 4047.31,790 R63.2@4047.31,814.14
IN2: J8.2 R57.2 R73.1 R76.2 | length 1771.5
  Top Layer w10: R57.2@4086.69,734.71 4086.97,735 R73.1@4135,735 ; R76.2@4135,574.69 R73.1@4135,735 ; R73.1@4135,735.32 R73.1@4135,735 ; v1(4160,735) R73.1@4135,735 ; J8.2@5528.5,935.83 5530,937.33 v1(5530,995)
  Signal Layer 2 w10: v1(4160,735) 4850,735 5110,995 v1(5530,995)
IN2_ATTN: C123.1 R57.1 R64.2 | length 97.3
  Top Layer w10: C123.1@3990.53,713 3992.38,714.86 4047.31,714.86 ; R64.2@4047.31,695 4047.31,714.86 ; R57.1@4047.31,734.71 4047.31,714.86
IN3: J4.2 J9.3 R59.2 R75.2 | length 1700.6
  Top Layer w10: R59.2@4086.69,933.29 4088.4,935 v1(4160,935) ; J9.3@5236.5,1684.5 5240,1681 v1(5240,1625)
  Signal Layer 2 w10: J4.2@4191,1122 4191,966 v1(4160,935) 4505,935 5195,1625 v1(5240,1625)
IN3_ATTN: C124.1 R59.1 R65.2 | length 96.9
  Top Layer w10: C124.1@3991.39,953.14 4047.31,953.14 ; 4046.46,954 4047.31,953.14 ; R59.1@4047.31,933.29 4047.31,953.14 ; R65.2@4047.31,973 4047.31,953.14
IN4: J9.2 R61.2 R74.1 R75.1 | length 1767.4
  Top Layer w10: R61.2@4086.69,893.57 4087.43,894.32 R75.1@4135,894.32 4135,875 4155,855 v1(4220,855) ; J9.2@5528.5,1365.5 5530,1367 v1(5530,1425)
  Signal Layer 2 w10: v1(4220,855) 4236,871 4590,871 5144,1425 v1(5530,1425)
IN4_ATTN: C132.1 R61.1 R66.2 | length 97.3
  Top Layer w10: C132.1@3992.53,875 4047.31,875 ; 4045.31,877 4047.31,875 ; R66.2@4047.31,853.86 4047.31,875 ; R61.1@4047.31,893.57 4047.31,875
IN5: J6.3 R39.2 R77.2 R78.2 | length 1259.2
  Top Layer w10: R39.2@4086.69,239.14 4087.23,239.69 R77.2@4135,239.69 4135,260 4151.31,276.31 R78.2@4194,276.31 4195.31,275 v1(4220,275) ; v1(5235,340) 5235,394 J6.3@5236.5,395.5
  Signal Layer 2 w10: v1(4220,275) 5170,275 v1(5235,340)
IN5_ATTN: C102.2 R39.1 R47.2 | length 95.6
  Top Layer w10: C102.2@3990.53,259 4046.74,259 4047.31,258.43 ; R39.1@4047.31,239.14 4047.31,258.43 ; R47.2@4047.31,277.71 4047.31,258.43
IN6: J6.2 R41.2 R77.1 | length 1529.6
  Top Layer w10: R41.2@4086.69,200.57 4087.26,200 v1(4160,200) ; J6.2@5528.5,76.5 5530,78 v1(5530,135)
  Signal Layer 2 w10: v1(4160,200) 4193,167 5238,167 5270,135 v1(5530,135)
IN6_ATTN: C103.2 R41.1 R48.2 | length 95.8
  Top Layer w10: C103.2@3990.53,181 4046.31,181 4047.31,180 ; R48.2@4047.31,162 4047.31,180 ; R41.1@4047.31,200.57 4047.31,180
IN7: J7.3 R43.2 R76.1 R79.2 | length 1500.7
  Top Layer w10: R43.2@4086.69,393.43 4088.26,395 R79.2@4135,395 ; R79.2@4135,394.69 R79.2@4135,395 ; R76.1@4135,535.32 R79.2@4135,395 ; v1(4160,395) R79.2@4135,395 ; v1(5235,770) 5235,823.67 J7.3@5236.5,825.17
  Signal Layer 2 w10: v1(4160,395) 4772,395 5147,770 v1(5235,770)
IN7_ATTN: C104.2 R43.1 R49.2 | length 96.2
  Top Layer w10: C104.2@3990.53,413 4045.31,413 4047.31,415 ; R43.1@4047.31,393.43 4047.31,415 ; R49.2@4047.31,432 4047.31,415
IN8: J7.2 R45.2 R78.1 R79.1 | length 1635.1
  Top Layer w10: R45.2@4086.69,354.86 4087.14,355.32 R79.1@4135,355.32 4135,335 4154.31,315.68 R78.1@4194,315.68 4194.69,315 v1(4220,315) ; J7.2@5528.5,506.17 5530,507.67 v1(5530,565)
  Signal Layer 2 w10: v1(4220,315) 4238,333 4863,333 5095,565 v1(5530,565)
IN8_ATTN: C112.2 R45.1 R50.2 | length 95.5
  Top Layer w10: C112.2@3990.53,336 4046.89,336 4047.31,335.57 ; R50.2@4047.31,316.29 4047.31,335.57 ; R45.1@4047.31,354.86 4047.31,335.57
LRCLK: TP15.1 U9.16 U10.5 | length 930.4
  Top Layer w10: U10.5@3097.41,1386.14 3097.41,1342.59 v1(3100,1340) ; TP15.1@3330,690 v1(3375,690) 3408.86,723.86 U9.16@3435.2,723.86
  Signal Layer 2 w10: v1(3100,1340) 3100,1325 3183.5,1241.5 3183.5,1139.5 3258,1065 3258,807 v1(3375,690)
LRCLK_B: R70.1 R71.1 R72.1 U10.6 | length 253.6
  Top Layer w10: R71.1@2969.69,1275 R71.1@2970,1275 ; R72.1@2970,1239.68 R71.1@2970,1275 ; R70.1@2970,1310.32 R71.1@2970,1275 ; U10.6@3071.82,1386.14 3071.82,1326.82 3020,1275 R71.1@2970,1275
LRCLK_P2: R72.2 U8.16 | length 1233.1
  Top Layer w10: v1(2970,1175) R72.2@2970,1200.31 ; v1(3410,175) 3410.86,175.86 U8.16@3435.2,175.86
  Signal Layer 2 w10: v1(2970,1175) 3145,1000 3145,720 3223,642 3223,546 3272.2,496.8 3272.2,312.8 v1(3410,175)
LRCLK_T1: R70.2 U1.14 | length 1647.7
  Top Layer w10: R70.2@2970,1349.69 2994.69,1349.69 v1(2995,1350)
  Signal Layer 2 w10: v1(2535,2645) 2633,2645 2756,2522 2756,1734 2995,1495 v1(2995,1350)
  Bottom Layer w10: U1.14@2461.01,2646.5 2538.5,2646.5 v1@2540,2645
LRCLK_T2: R71.2 U2.14 | length 705.5
  Top Layer w10: v1(2930,1300) 2930.31,1299.69 R71.2@2930.31,1278 R71.2@2930.31,1275
  Signal Layer 2 w10: v1(2535,962) 2543.49,962 2554.49,951 2687,951 2905,1169 2905,1275 v1(2930,1300)
  Bottom Layer w10: U2.14@2461.01,962.5 2534.5,962.5 v1(2535,962)
NetC14_2: C14.2 U1.54 | length 164.9
  Bottom Layer w10: C14.2@1959.53,2978 1990,2978 2008,2960 2008,2936 2022.5,2921.5 U1.54@2086.99,2921.5
NetC16_2: C16.2 U1.50 | length 299.9
  Bottom Layer w10: C16.2@1833.47,2845 1833.47,2808.53 1839,2803 1998,2803 2016.5,2821.5 U1.50@2086.99,2821.5
NetC19_2: C19.2 U1.48 | length 294.6
  Bottom Layer w10: C19.2@1833.47,2744 1833.47,2776.47 1841.36,2784.36 1997.64,2784.36 2010.5,2771.5 U1.48@2086.99,2771.5
NetC21_1: C21.1 U1.5 | length 92.1
  Bottom Layer w10: U1.5@2461.01,2871.5 2550.94,2871.5 C21.1@2552.44,2870
NetC22_2: C22.2 U1.44 | length 147.1
  Top Layer w10: v1(2005,2667) 2022.47,2684.47 C22.2@2061,2684.47
  Bottom Layer w10: v1(2005,2667) 2009.5,2671.5 U1.44@2086.99,2671.5
NetC23_1: C23.1 U1.6 | length 216
  Bottom Layer w10: U1.6@2461.01,2846.5 2518.5,2846.5 2525,2840 2590,2840 2610,2820 2662.44,2820 C23.1@2665,2817.44
NetC24_1: C24.1 U1.8 | length 96.2
  Bottom Layer w10: U1.8@2461.01,2796.5 2540.94,2796.5 C24.1@2552.44,2785
NetC27_2: C27.2 U1.41 | length 140.8
  Top Layer w10: v1(2008,2601.69) 2024.16,2585.53 C27.2@2061,2585.53
  Bottom Layer w10: v1(2008,2601.69) 2013.19,2596.5 U1.41@2086.99,2596.5
NetC28_2: C28.2 U1.37 | length 299.5
  Bottom Layer w10: C28.2@1833.47,2520 1833.47,2485.53 1842.2,2476.8 1963,2476.8 ; 1963.2,2477 1994,2477 2013.5,2496.5 U1.37@2086.99,2496.5
NetC29_1: C29.1 U1.9 | length 161
  Bottom Layer w10: U1.9@2461.01,2771.5 2513.5,2771.5 2550,2735 C29.1@2606.84,2735
NetC30_1: C30.1 U1.10 | length 171.5
  Bottom Layer w10: U1.10@2461.01,2746.5 2508.5,2746.5 2569.59,2685.41 C30.1@2607.25,2685.41
NetC33_2: C33.2 U1.35 | length 295.3
  Bottom Layer w10: C33.2@1833.47,2418 1833.47,2451.47 1841,2459 1994,2459 2006.5,2446.5 U1.35@2086.99,2446.5
NetC34_2: C34.2 U1.31 | length 220.8
  Bottom Layer w10: C34.2@1889,2291.47 1953.47,2291.47 2008.5,2346.5 U1.31@2086.99,2346.5
NetC54_2: C54.2 U2.54 | length 164.9
  Bottom Layer w10: C54.2@1959.53,1294 1990,1294 2008,1276 2008,1252 2022.5,1237.5 U2.54@2086.99,1237.5
NetC56_2: C56.2 U2.50 | length 300.6
  Bottom Layer w10: C56.2@1833.47,1161 1833.47,1124.53 1839.84,1118.16 1997.16,1118.16 2016.5,1137.5 U2.50@2086.99,1137.5
NetC59_2: C59.2 U2.48 | length 294.6
  Bottom Layer w10: C59.2@1833.47,1060 1833.47,1092.47 1841.36,1100.36 1997.64,1100.36 2010.5,1087.5 U2.48@2086.99,1087.5
NetC61_1: C61.1 U2.5 | length 92.1
  Bottom Layer w10: U2.5@2461.01,1187.5 2550.94,1187.5 C61.1@2552.44,1186
NetC62_2: C62.2 U2.44 | length 146.3
  Top Layer w10: v1(2005,983) 2020.47,998.47 C62.2@2061,998.47
  Bottom Layer w10: v1(2005,983) 2009.5,987.5 U2.44@2086.99,987.5
NetC63_1: C63.1 U2.6 | length 216
  Bottom Layer w10: U2.6@2461.01,1162.5 2518.5,1162.5 2525,1156 2590,1156 2610,1136 2662.44,1136 C63.1@2665,1133.44
NetC66_1: C66.1 U2.8 | length 96.2
  Bottom Layer w10: U2.8@2461.01,1112.5 2540.94,1112.5 C66.1@2552.44,1101
NetC67_2: C67.2 U2.41 | length 139.2
  Top Layer w10: v1(2008,917.69) 2017.69,908 2058.53,908 C67.2@2061,905.53
  Bottom Layer w10: v1(2008,917.69) 2013.19,912.5 U2.41@2086.99,912.5
NetC68_2: C68.2 U2.37 | length 299.8
  Bottom Layer w10: C68.2@1833.47,836 1833.47,801.53 1842.2,792.8 1963,792.8 1963.2,793 1994,793 2013.5,812.5 U2.37@2086.99,812.5
NetC69_1: C69.1 U2.9 | length 161.2
  Bottom Layer w10: U2.9@2461.01,1087.5 2513.5,1087.5 2550,1051 2577.44,1051 ; 2577.63,1050.81 C69.1@2607.25,1050.81
NetC70_1: C70.1 U2.10 | length 171
  Bottom Layer w10: U2.10@2461.01,1062.5 2508.5,1062.5 2568.19,1002.81 C70.1@2607.25,1002.81
NetC73_2: C73.2 U2.35 | length 295.3
  Bottom Layer w10: C73.2@1833.47,734 1833.47,767.47 1841,775 1994,775 2006.5,762.5 U2.35@2086.99,762.5
NetC74_2: C74.2 U2.31 | length 220.8
  Bottom Layer w10: C74.2@1889,607.47 1953.47,607.47 2008.5,662.5 U2.31@2086.99,662.5
NetC81_2: C81.2 C147.1 | length 80.4
  Top Layer w12: C81.2@1141,3946.31 1141.32,3946 C147.1@1141.32,3866
NetC84_1: C84.1 R9.1 | length 41.9
  Top Layer w10: R9.1@2887.44,3599.13 C84.1@2887.44,3641
NetC94_1: C94.1 U3.1 | length 125.4
  Top Layer w19: 2898,3766.94 U3.1@2940.26,3809.2
  Top Layer w20: C94.1@2891.53,3704 2898,3710.47 2898,3766.94
NetC98_2: C98.2 R13.2 | length 54.8
  Bottom Layer w10: C98.2@3242.56,3886 R13.2@3297.31,3886
NetC102_1: C102.1 R40.1 | length 63
  Top Layer w10: R40.1@3876.69,239.14 3911.62,239.14 C102.1@3931.47,259
NetC103_1: C103.1 R42.1 | length 62.9
  Top Layer w10: R42.1@3876.69,200.57 3911.9,200.57 C103.1@3931.47,181
NetC104_1: C104.1 R44.1 | length 62.9
  Top Layer w10: R44.1@3876.69,393.43 3911.9,393.43 C104.1@3931.47,413
NetC107_1: C107.1 U8.29 | length 89.3
  Top Layer w10: U8.29@3691.11,175.86 3691.11,208.11 3710,227 v1(3715,227)
  Bottom Layer w10: v1(3715,227) C107.1@3715,252.32
NetC108_1: C108.1 U8.30 | length 106.2
  Top Layer w10: U8.30@3710.8,175.86 3733.86,175.86 v1(3735,177)
  Bottom Layer w10: v1(3735,177) 3750,192 C108.1@3750,252.32
NetC109_1: C109.1 U8.27 | length 79.2
  Top Layer w10: v1(3645,227) 3651.74,220.26 U8.27@3651.74,175.86
  Bottom Layer w10: v1(3645,227) C109.1@3645,252.32
NetC110_1: C110.1 U8.28 | length 72.9
  Top Layer w10: U8.28@3671.43,175.86 3671.43,223.43 v1(3675,227)
  Bottom Layer w10: v1(3675,227) C110.1@3675,247.32
NetC111_1: C111.1 U8.6 | length 81.8
  Top Layer w10: U8.6@3612.37,408.14 3612.37,444.37 3637.5,469.5 C111.1@3637.5,479.5
NetC112_1: C112.1 R46.1 | length 62.6
  Top Layer w10: R46.1@3876.69,354.86 3912.62,354.86 C112.1@3931.47,336
NetC119_1: C119.1 J3.2 R83.2 U4.8 | length 896.9
  Top Layer w10: R83.2@4153,1983.69 4213.31,1983.69 v1(4215,1982)
  Top Layer w20: U4.8@4160,1528.72 4189.72,1528.72 4226,1565 C119.1@4226,1596.44 4283.56,1596.44 v1(4285,1595)
  Signal Layer 2 w20: J3.2@4211,2190 4211,1986 v1(4215,1982) 4329,1868 4329,1639 v1(4285,1595)
NetC122_2: C122.2 R56.1 | length 62.3
  Top Layer w10: R56.1@3876.69,774.43 3909.9,774.43 C122.2@3930.47,795
NetC123_2: C123.2 R58.1 | length 63.8
  Top Layer w10: R58.1@3876.69,734.71 3909.76,734.71 C123.2@3931.47,713
NetC124_2: C124.2 R60.1 | length 63.4
  Top Layer w10: R60.1@3876.69,933.29 3910.76,933.29 C124.2@3931.47,954
NetC127_1: C127.1 U9.29 | length 89.3
  Top Layer w10: U9.29@3691.11,723.86 3691.11,756.11 3710,775 v1(3715,775)
  Bottom Layer w10: v1(3715,775) C127.1@3715,800.32
NetC128_1: C128.1 U9.30 | length 106.2
  Top Layer w10: U9.30@3710.8,723.86 3733.86,723.86 v1(3735,725)
  Bottom Layer w10: v1(3735,725) 3750,740 C128.1@3750,800.32
NetC129_1: C129.1 U9.27 | length 79.2
  Top Layer w10: v1(3645,775) 3651.74,768.26 U9.27@3651.74,723.86
  Bottom Layer w10: v1(3645,775) C129.1@3645,800.32
NetC130_1: C130.1 U9.28 | length 72.9
  Top Layer w10: U9.28@3671.43,723.86 3671.43,771.43 v1(3675,775)
  Bottom Layer w10: v1(3675,775) C130.1@3675,795.32
NetC131_1: C131.1 U9.6 | length 81.8
  Top Layer w10: U9.6@3612.37,956.14 3612.37,992.37 3637.5,1017.5 C131.1@3637.5,1027.5
NetC132_2: C132.2 R62.1 | length 61.5
  Top Layer w10: R62.1@3876.69,893.57 3911.9,893.57 C132.2@3930.47,875
NetC141_1: C141.1 R23.1 U4.6 U4.7 | length 182.5
  Top Layer w10: C141.1@4026.69,1437 4065.31,1437 4065.31,1470.68 4060,1476 U4.6@4060,1528.72 U4.7@4110,1528.72
NetC141_2: C141.2 R27.2 R32.1 | length 294.2
  Top Layer w10: 3914,1439 3882.2,1470.8 3882.2,1580.2 3898.31,1596.31 R27.2@3948,1596.31 ; 3919.69,1437.32 R32.1@3948,1437.32 ; R32.1@3948.31,1437 C141.2@3987.31,1437
NetC144_1: C144.1 R19.1 U6.1 | length 109.8
  Top Layer w10: C144.1@3599.44,3540 C144.1@3602.31,3537.13
  Top Layer w12: C144.1@3599.44,3540 3616.41,3556.97 U6.1@3616.41,3591.61
  Top Layer w20: R19.1@3602.31,3490 C144.1@3602.31,3537.13
NetC147_2: C147.2 C151.2 R86.2 | length 203.7
  Top Layer w12: C147.2@1180.69,3866 1180.69,3852.31 1208.5,3824.5 ; R86.2@1208.5,3758 1208.5,3824.5 ; C151.2@1219.69,3904 1219.69,3835.69 1208.5,3824.5
NetC148_1: C148.1 R2.1 U4.2 | length 113.7
  Top Layer w10: U4.2@4110,1743.28 4110,1783 4113.31,1786.32 R2.1@4113.31,1814 4113.31,1854.63 C148.1@4114,1855.31
NetC149_1: C149.1 R32.2 U4.5 | length 105.6
  Top Layer w10: R32.2@3948,1476.69 C149.1@3948,1514.32 3995.6,1514.32 U4.5@4010,1528.72
NetC150_2: C150.2 C151.1 | length 40
  Top Layer w12: C151.1@1180.32,3904 C150.2@1180.32,3944
NetC152_1: C152.1 U11.7 | length 143.1
  Top Layer w10: U11.7@2114.8,3866.34 2114.8,3900.74 2142.53,3928.47 C152.1@2212,3928.47
NetC152_2: C152.2 U11.1 | length 110.1
  Top Layer w10: U11.1@2140.39,4033.66 2140.39,4000.65 2153.51,3987.53 C152.2@2212,3987.53
NetC153_2: C153.2 U12.1 | length 179.5
  Top Layer w10: v1(1943,3971) C153.2@1943,4021.47
  Bottom Layer w10: v1(1943,3971) 2001.4,3912.6 U12.1@2047.87,3912.6
NetD1_2: D1.2 R10.2 | length 1384.3
  Top Layer w10: R10.2@4324.69,3365 4326.69,3363 v1(4364,3363) ; D1.2@5163.5,2683 v1(5163.5,2753)
  Signal Layer 2 w10: v1(4364,3363) 4364,2984 4595,2753 v1(5163.5,2753)
NetD2_2: D2.2 R11.2 | length 1428.5
  Top Layer w10: R11.2@4324.69,3408 4367,3408 v1(4368,3409) ; D2.2@5161,2894.5 D2.2@5163.5,2892 ; v1(5163,2832) D2.2@5163,2891.5
  Signal Layer 2 w10: v1(4368,3409) 4397,3380 4397,2985 4611,2771 5112,2771 5163,2822 v1(5163,2832)
NetD5_2: D5.2 D6.2
NetD7_2: D7.2 R25.1 | length 1308.9
  Top Layer w10: v1(4469,3694) R25.1@4469,3740.31 ; v1@5076.88,3046.88 v1(5076.88,3051) D7.2@5076.88,3116
  Signal Layer 2 w10: v1(4469,3694) 4469,3149 4567,3051 v1(5076.88,3051)
NetJ4_1: J4.1 R23.2 R82.2 | length 277.8
  Top Layer w10: R23.2@4105.69,1436 R82.2@4154.31,1436 4154.31,1399 4191,1362.31 J4.1@4191,1222
NetJ5_2: J5.2 R31.1 | length 108.4
  Top Layer w20: R31.1@3715,4181.56 J5.2@3715,4290
NetQ1_4: Q1.4 U11.2 U11.6 U12.5 | length 365.9
  Top Layer w10: U11.6@2089.2,3866.34 2089.2,3941.61 v1@2114.8,3967.2 ; v1(2116,3966) v1@2114.8,3967.2 ; Q1.4@2211.75,4082 2210.75,4083 2127,4083 2114.8,4070.8 U11.2@2114.8,4033.66 v1@2114.8,3967.2
  Bottom Layer w10: v1(2116,3966) 2132,3950 U12.5@2156.13,3950
NetR2_2: R2.2 R27.1 R84.2 U4.1 | length 484
  Top Layer w10: R27.1@3948,1635.68 3986.31,1635.68 v1(4004,1618) ; R84.2@4152.69,1855 R2.2@4152.69,1814 4152.69,1784.31 4160,1777 U4.1@4160,1743.28 4165.28,1738 v1(4209,1738)
  Signal Layer 2 w10: v1(4004,1618) 4074,1618 4194,1738 v1(4209,1738)
NetR26_1: R26.1 U3.18 | length 94.7
  Top Layer w10: R26.1@2839.69,3940 2890,3940 2906.63,3923.37 U3.18@2927.46,3923.37
NetR83_1: R83.1 R84.1 R85.2 U4.3 | length 359.5
  Top Layer w10: U4.3@4060,1743.28 4060,1945 4078,1963 4117,1963 4135.69,1944.32 R83.1@4153,1944.32 R84.1@4153,1894.68
NetTP8_1: TP8.1 U7.5 | length 106.2
  Top Layer w10: U7.5@4087.2,3618.86 4087.2,3537.8 TP8.1@4105,3520
NetTP9_1: TP9.1 U7.4 | length 105.8
  Top Layer w10: TP9.1@4040,3522 4061.61,3543.61 U7.4@4061.61,3618.86
NFAULT: D1.1 U1.26 U2.26 U7.8 | length 6547.5
  Top Layer w10: v1(3150,3302) 3162.2,3289.8 3609.8,3289.8 3620,3300 4068,3300 v1(4101,3267) ; v1(4163.98,3507) U7.8@4163.98,3618.86 ; v1(5036,2685) 5038,2683 D1.1@5100.5,2683 5100.5,2813.5 v1@5101,2814
  Signal Layer 2 w10: v1@2384,660 2344,660 2266,738 2266,1473 2458,1665 2458,2306 2418,2346 v1(2383,2346) 2346,2383 2346,3102.83 2566.37,3323.2 3129.8,3323.2 3150,3303 v1(3150,3302) ; v1@4163.98,3496.98 4101,3434 v1(4101,3267) 4101,3114 4555,2660 4727,2660 4752,2685 v1(5036,2685)
  Bottom Layer w10: v1(2383,662) 2383.5,662.5 U2.26@2461.01,662.5 ; v1(2383,2346) 2383.5,2346.5 U1.26@2461.01,2346.5
  other v1: 5101,2819
NMUTE: R5.1 U1.25 U2.25 | length 2155.4
  Signal Layer 2 w10: v1@2406,686 2363,686 2301,748 2301,1463 2488,1650 2488,2306 2424,2370 v1@2406,2370
  Bottom Layer w10: v1@2405,687 2405.5,687.5 U2.25@2461.01,687.5 ; v1@2405,2371 2405.5,2371.5 U1.25@2461.01,2371.5 2516.5,2371.5 2577,2311 R5.1@2604.32,2311
  other v1: 2405,688 2405,2372
NRESET_PS: R34.1 U3.19 | length 1298.7
  Top Layer w10: v1(2871,3914) 2886,3914 2896.31,3903.69 U3.19@2927.46,3903.69 ; v1(4066,3957) 4066.31,3956.69 R34.1@4066.31,3932
  Signal Layer 2 w10: v1(2871,3914) 2905.2,3948.2 4057.2,3948.2 v1(4066,3957)
NRST_TDIO: C96.1 J5.4 R33.1 R34.2 S1.1 U7.16 | length 1150.7
  Top Layer w10: R33.1@3779,3747.69 3779,3781.53 3768.51,3792.01 3768.51,3844.51 3783.2,3859.2 3783.2,3859.37 3808.63,3884.8 3894,3884.8 3983.8,3795 4080,3795 4087.2,3802.2 U7.16@4087.2,3851.14 4087.2,3893.2 4105.69,3911.69 R34.2@4105.69,3932 C96.1@4105.69,3972.63 ; J5.4@3813,4294 3813,4199 3917.5,4094.5 3917.5,4071.5 3948,4041 S1.1@3978.68,4041 4037.31,4041 C96.1@4105.69,3972.63 ; C96.1@4106.31,3972 C96.1@4105.69,3972.63
NSTANDBY: R6.1 U1.24 U2.24 | length 2187.9
  Signal Layer 2 w10: v1(2383,2396) 2428,2396 ; v1@2384,710 2331,763 2331,1443 2518,1630 2518,2306 2430,2394 2428,2394
  Bottom Layer w10: v1(2383,712) 2383.5,712.5 U2.24@2461.01,712.5 ; v1(2383,2396) 2383.5,2396.5 U1.24@2461.01,2396.5 2533.5,2396.5 2585,2345 R6.1@2604.32,2345
NWARN: D2.1 U1.27 U2.27 U7.9 | length 6590.7
  Top Layer w10: v1(3178,3341) 3210,3309 3589.2,3309 3598,3317.8 4101.2,3317.8 v1(4134,3285) ; v1(4189.57,3532) U7.9@4189.57,3618.86 ; D2.1@5100.5,2892 5101,2892.5 v1(5101,2924)
  Signal Layer 2 w10: v1(2404,637) 2322,637 2241,718 2241,1488 2427,1674 2427,2298 v1(2404,2321) 2359,2321 2324,2356 2324,3106 2559,3341 v1(3178,3341) ; v1(4134,3285) 4135,3286 4135,3430 4189.57,3484.57 v1(4189.57,3532) 4373,3532 4448,3457 4448,3033 4557,2924 v1(5101,2924) v1@5096,2929
  Bottom Layer w10: v1(2404,637) 2404.5,637.5 U2.27@2461.01,637.5 ; v1(2404,2321) 2404.5,2321.5 U1.27@2461.01,2321.5
OUT1+: C77.1 C78.1 J2.2 L8.2 | length 68.6
  Bottom Layer w10: J2.2@423,561.51 462.17,561.51 C78.1@483,540.68
  other v1: 1185,385 1185,410 1185,435 1185,460 1185,485
OUT1-: C79.1 C80.1 J2.1 L8.3 | length 63.1
  Bottom Layer w10: J2.1@423,423.72 475.4,423.72 C80.1@483,431.32
  other v1: 1185,115 1185,140 1185,165 1185,190 1185,215
OUT1M: C34.1 L4.4 U1.32 | length 49.9
  Bottom Layer w10: C34.1@1889,2350.53 1898.47,2360 v1(1935,2360)
  other v1: 1650,1810 1650,1835 1650,1860 1650,1885 1650,1910 1950,2340 1970,2350 1955,2375 1980,2375
OUT1P: C33.1 L4.1 U1.34
  other v1: 1650,2075 1650,2100 1650,2125 1650,2150 1650,2175 1930,2413 1955,2413 1980,2413 1943,2433 1967,2433
OUT2+: C71.1 C72.1 J2.4 L7.2 | length 65.6
  Bottom Layer w10: J2.4@423,837.1 469.58,837.1 C72.1@483,823.68
  other v1: 1185,810 1185,835 1185,860 1185,885 1185,910
OUT2-: C75.1 C76.1 J2.3 L7.3 | length 67.5
  Bottom Layer w10: J2.3@423,699.31 464.99,699.31 C76.1@483,717.32
  other v1: 1185,540 1185,565 1185,590 1185,615 1185,640
OUT2M: C28.1 L3.4 U1.38
  other v1: 1650,2235 1650,2260 1650,2285 1650,2310 1650,2335 1943,2507 1967,2507 1930,2527 1955,2527 1980,2527
OUT2P: C27.1 L3.1 U1.40 | length 97
  Top Layer w10: v1(1980,2565) 2018.53,2526.47 C27.1@2061,2526.47
  other v1: 1650,2505 1650,2530 1650,2555 1930,2565 1955,2565 1650,2580 1943,2585 1967,2585 1650,2605
OUT3+: C57.1 C58.1 J2.6 L6.2 | length 69.5
  Bottom Layer w10: J2.6@423,1112.69 459.99,1112.69 C58.1@483,1089.68
  other v1: 1185,1230 1185,1255 1185,1280 1185,1305 1185,1330
OUT3-: C64.1 C65.1 J2.5 L6.3 | length 61.4
  Bottom Layer w10: J2.5@423,974.9 479.58,974.9 C65.1@483,978.32
  other v1: 1185,965 1185,990 1185,1015 1185,1040 1185,1065
OUT3M: C22.1 L2.4 U1.45 | length 99
  Top Layer w10: v1(1980,2700) 1985,2700 2028.53,2743.53 C22.1@2061,2743.53
  other v1: 1650,2660 1943,2679 1967,2679 1650,2685 1955,2700 1931,2701 1650,2710 1650,2735 1650,2760
OUT3M2: C62.1 L6.4 U2.45 | length 98.2
  Top Layer w10: v1(1980,1016) 2001,1016 2042.53,1057.53 C62.1@2061,1057.53
  other v1: 1650,965 1650,990 1943,995 1967,995 1650,1015 1955,1016 1931,1017 1650,1040 1650,1065
OUT3P: C19.1 L2.1 U1.47
  other v1: 1931,2733 1955,2733 1980,2733 1943,2758 1970,2758 1650,2930 1650,2955 1650,2980 1650,3005 1650,3030
OUT3P2: C59.1 L6.1 U2.47
  other v1: 1931,1049 1955,1049 1980,1049 1943,1074 1970,1074 1650,1235 1650,1260 1650,1285 1650,1310 1650,1335
OUT4+: C42.1 C43.1 J2.8 L5.2 | length 67.7
  Bottom Layer w10: J2.8@423,1388.28 464.4,1388.28 C43.1@483,1369.68
  other v1: 1185,1660 1185,1685 1185,1710 1185,1735 1185,1760
OUT4-: C52.1 C53.1 J2.7 L5.3 | length 64.1
  Bottom Layer w10: J2.7@423,1250.49 473.17,1250.49 C53.1@483,1260.32
  other v1: 1185,1390 1185,1415 1185,1440 1185,1465 1185,1490
OUT4M: C16.1 L1.4 U1.51
  other v1: 1943,2832 1970,2832 1931,2857 1955,2857 1980,2857 1650,3085 1650,3110 1650,3135 1650,3160 1650,3185
OUT4M2: C56.1 L5.4 U2.51
  other v1: 1943,1148 1970,1148 1931,1173 1955,1173 1980,1173 1650,1390 1650,1415 1650,1440 1650,1465 1650,1490
OUT4P: C14.1 L1.1 U1.53
  other v1: 1955,2890 1980,2890 1934,2903 1955,2915 1980,2915 1650,3350 1650,3375 1650,3400 1650,3425 1650,3450
OUT4P2: C54.1 L5.1 U2.53
  other v1: 1955,1206 1980,1206 1934,1219 1955,1231 1980,1231 1650,1655 1650,1680 1650,1705 1650,1730 1650,1755
OUT5+: C37.1 C38.1 J1.2 L4.2 | length 67.8
  Bottom Layer w10: J1.2@431,2271.51 472.17,2271.51 C38.1@491,2252.69
  other v1: 1185,2080 1185,2105 1185,2130 1185,2155 1185,2180
OUT5-: C39.1 C40.1 J1.1 L4.3 | length 63.1
  Bottom Layer w10: J1.1@431,2133.72 483.4,2133.72 C40.1@491,2141.31
  other v1: 1185,1815 1185,1840 1185,1865 1185,1890 1185,1915
OUT6+: C31.1 C32.1 J1.4 L3.2 | length 66.4
  Bottom Layer w10: J1.4@431,2547.1 475.58,2547.1 C32.1@491,2531.69
  other v1: 1185,2505 1185,2530 1185,2555 1185,2580 1185,2605
OUT6-: C35.1 C36.1 J1.3 L3.3 | length 67
  Bottom Layer w10: J1.3@431,2409.31 473.99,2409.31 C36.1@491,2426.31
  other v1: 1185,2240 1185,2265 1185,2290 1185,2315 1185,2340
OUT7+: C17.1 C18.1 J1.6 L2.2 | length 67
  Bottom Layer w10: J1.6@431,2822.69 473.99,2822.69 C18.1@491,2805.69
  other v1: 1185,2930 1185,2955 1185,2980 1185,3005 1185,3030
OUT7-: C25.1 C26.1 J1.5 L2.3 | length 65.6
  Bottom Layer w10: J1.5@431,2684.9 477.58,2684.9 C26.1@491,2698.31
  other v1: 1185,2665 1185,2690 1185,2715 1185,2740 1185,2765
OUT8+: C10.1 C11.1 J1.8 L1.2 | length 64.4
  Bottom Layer w10: J1.8@431,3098.28 480.4,3098.28 C11.1@491,3087.69
  other v1: 1185,3355 1185,3380 1185,3405 1185,3430 1185,3455
OUT8-: C12.1 C13.1 J1.7 L1.3 | length 67.4
  Bottom Layer w10: J1.7@431,2960.49 473.17,2960.49 C13.1@491,2978.31
  other v1: 1185,3082 1185,3107 1185,3132 1185,3157 1185,3182
OUTCM: C68.1 L7.4 U2.38
  other v1: 1650,540 1650,565 1650,590 1650,615 1650,640 1943,823 1967,823 1930,843 1955,843 1980,843
OUTCP: C67.1 L7.1 U2.40 | length 95.3
  Top Layer w10: v1(1980,881) 1989,881 2023.53,846.47 C67.1@2061,846.47
  other v1: 1650,810 1650,835 1650,860 1930,881 1955,881 1650,885 1943,901 1967,901 1650,910
OUTSM: C74.1 L8.4 U2.32 | length 49.9
  Bottom Layer w10: C74.1@1889,666.53 1898.47,676 v1(1935,676)
  other v1: 1650,115 1650,140 1650,165 1650,190 1650,215 1950,656 1970,666 1955,691 1980,691
OUTSP: C73.1 L8.1 U2.34
  other v1: 1650,380 1650,405 1650,430 1650,455 1650,480 1930,729 1955,729 1980,729 1943,749 1967,749
PS_SYNC: R20.2 U3.3 U7.6 | length 1907.8
  Top Layer w10: v1(2961,3744) 2975.31,3744 R20.2@2987,3755.69 2987,3775 2996.36,3784.36 U3.3@2996.36,3809.2 ; v1@4112.8,3559.2 U7.6@4112.8,3618.86
  Signal Layer 2 w10: v1(2961,3744) 2961,3768 3106,3913 4061,3913 4079.5,3931.5 4205.5,3931.5 4221,3916 4221,3844.49 4153.2,3776.69 4153.2,3776.2 4113,3736 v1(4113,3559)
PVDD: C1.1 C2.1 C3.1 C4.1 C5.1 C6.1 C7.1 C8.1 C9.1 C41.1 C44.1 C45.1 C46.1 C47.1 C48.1 C49.1 C50.1 C51.1 C85.1 C86.1 C87.1 C88.1 C89.1 C90.1 Q1.5 Q1.6 Q1.7 Q1.8 Q1.9 R1.1 R12.1 R24.1 R26.2 U1.2 U1.29 U1.30 U1.42 U1.43 U1.55 U1.56 U2.2 U2.29 U2.30 U2.42 U2.43 U2.55 U2.56 U3.4 U3.14 U3.15 U11.8 U12.4 | length 1727.7
  Top Layer w10: v1@1954,950 v1@1955,951 ; v1@1954,2634 v1@1955,2635 ; U3.4@3028.84,3817.07 3028.84,3826.16 3016,3839 2981,3839 2966,3854 2966,3907.84 2987.16,3929 3016,3929 3028.84,3941.84 U3.14@3028.84,3950.93
  Top Layer w15: U11.8@2140.39,3866.34 2283.66,3866.34
  Bottom Layer w10: v1@2059,495 v1(2060,496) ; U2.42@2086.99,937.5 2048.5,937.5 2035,951 2046.5,962.5 U2.43@2086.99,962.5 ; U1.42@2086.99,2621.5 2048.5,2621.5 2035,2635 2046.5,2646.5 U1.43@2086.99,2646.5 ; C51.1@2539.18,1262.5 C51.1@2541,1264.32 ; C9.1@2539.18,2946.5 C9.1@2541,2948.31
  Bottom Layer w12: v1(1980,950) 2035,950 ; v1(1980,2634) 2035,2634
  Bottom Layer w16: U2.2@2461.01,1262.5 C51.1@2539.18,1262.5 ; U1.2@2461.01,2946.5 C9.1@2539.18,2946.5
  Bottom Layer w22: C47.1@1865.68,950 v1(1900.68,950) v1(1927.12,950) v1(1953.56,950) v1(1980,950) ; C5.1@1870.68,2634 v1(1927.12,2634) v1(1953.56,2634) v1(1980,2634) ; 2105.68,3172 2105.68,3119.31 v1(2110,3115) ; U12.4@2156.13,3987.4 2314.4,3987.4 v1(2316,3989) ; 2580,1402 2585,1407 2682,1407 2704,1385 R12.1@2704,1302.53 ; 2588,3078 2678,3078 2711,3045 R1.1@2711,2985.53
  other v1: 2110,465 2060,466 2110,495 2110,525 2060,526 2565,1263 2590,1263 2570,1330 2595,1330 2110,1370 2055,1371 2110,1400 2055,1401 2110,1430 2055,1431 2570,1470 2595,1470 2060,2150 2110,2150 2060,2180 2110,2180 2060,2210 2110,2210 1900.68,2634 2565,2947 2590,2947 2570,3010 2595,3010 2055,3055 2110,3055 2055,3085 2110,3085 2055,3115 2570,3150 2595,3150
SBWTCK: J5.3 U7.17 | length 577.5
  Top Layer w10: J5.3@3765,4290 3765,4209 3894,4080 3894,4032 4009,3917 4036,3917 4061.61,3891.39 U7.17@4061.61,3851.14
SCL: R29.1 TP7.1 U1.20 U2.20 U7.14 U8.24 U9.24 | length 8710.6
  Top Layer w10: v1(3510,800) 3565,800 3592.69,772.31 U9.24@3592.69,723.86 ; v1(3580,250) 3592.69,237.31 U8.24@3592.69,175.86 ; R29.1@3856,3747.69 3856,3767 ; v1@3867,3778 TP7.1@3867,3817 3901,3817 3999.5,3718.5 4056.5,3718.5 4068.2,3730.2 4069.17,3730.2 v1@4138.39,3799.42 ; U7.14@4138.39,3851.14 v1@4138.39,3799.42 ; v1(4139,3801) 4139,3800.03 v1@4138.39,3799.42
  Signal Layer 2 w10: v1(2405,813) 2405,1429 2578,1602 2578,2324 v1(2405,2497) 2405,2597 3024,3216 3201,3216 3275,3290 3275,3406.83 3645.17,3777 v1(3864,3777) ; v1(3580,250) 3445,385 3445,680 3510,745 v1(3510,800) 3510,871 3413,968 3413,1395.2 3908.8,1891 3908.8,3237.63 4062.17,3391 4062.17,3725.17 v1@4138.5,3801.5
  Bottom Layer w10: v1(2405,813) 2405.5,812.5 U2.20@2461.01,812.5 ; v1(2405,2497) 2405.5,2496.5 U1.20@2461.01,2496.5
